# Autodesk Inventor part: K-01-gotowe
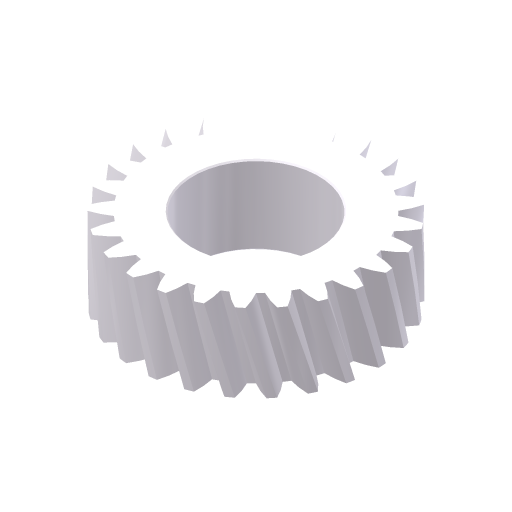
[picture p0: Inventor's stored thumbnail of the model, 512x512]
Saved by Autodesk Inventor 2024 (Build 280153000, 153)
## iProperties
Company: ATC
CustomPartVersion: 1
Created: 2023-03
Part Number: K-01-gotowe
Material: Stal kuta
Document SubType Name: Modeling
Designer: Andrzej Jaskulski
Categories: <?xml version="1.0" encoding="UTF-16"?> <MemberInstance><Categories><FamilyTemplate><FamilyTemplateParameter ValueType="xs:double" Id="1" ObjectReferenceKey="da
Density: 1 g/cm^3
Stock Number: K-01-gotowe
Appearance: Stal
Checked By: A.J.
Engr Approved By: Andrzej Jaskulski
Mfg Approved By: Andrzej Jaskulski
Authority: A.J.
Title: A.J.: Kurs R2024-MEP
Author: Andrzej Jaskulski
Revision Number: 1/24
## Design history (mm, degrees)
sketch "Sketch1"
  geometry: C1 r 76.136 at (0, 0)
  constraints: 1 centre point
  dimensions: "d0" = 152.27143 diameter of C1 (= da_da)
extrude "Extrusion1" new body sketch "Sketch1" distance "d1" = 50 (= da_b); taper "d2" = 0 deg
workplane "Work Plane2"
feature "Średnica podziałowa" dims "d4" = 10, "d5" = 0
workplane "Work Plane8"
workplane "Work Plane9"
feature "Przekładnia zębata czołowa" dims "da_b" = 50, "da_d" = 142.35047, "da_aw" = 180, "da_da" = 152.27143, "da_df" = 128.60047, "da_dw" = 138.46154, angle "da_beta" = 15 deg, "da_lefttooth" = 10, "da_righttooth" = 0
hole "Otwory1" diameter "d51" = 80; stored, may be unused: countersink angle "d55" = 90 deg, drill point angle "d57" = 118 deg; dims "d49" = 10, "d50" = 10, "d52" = 6, "d53" = 4, "d54" = 2, "d56" = 8
chamfer "Faza1" distance "d58" = 0.8; stored, may be unused: second distance "d59" = 2, angle "d60" = 45 deg
node "Bryła1"
node "Korpusy bryłowe"
node "Korpusy powierzchniowe"
sketch "Sketch2"
  geometry: C1 r 76.136 at (0, 0) reference; C2 r 69.231 at (0, 0)
  constraints: 1 centre point, 1 coincident
  dimensions: "d3" = 138.46154 diameter of C2 (= da_dw)
body "Srf1"
other parameters: "d17" = 0, "d34" = 1.25664 (computed from da_z), "d39" = 0, "d41" = 0, "d47" = 0, "d48" = 0
